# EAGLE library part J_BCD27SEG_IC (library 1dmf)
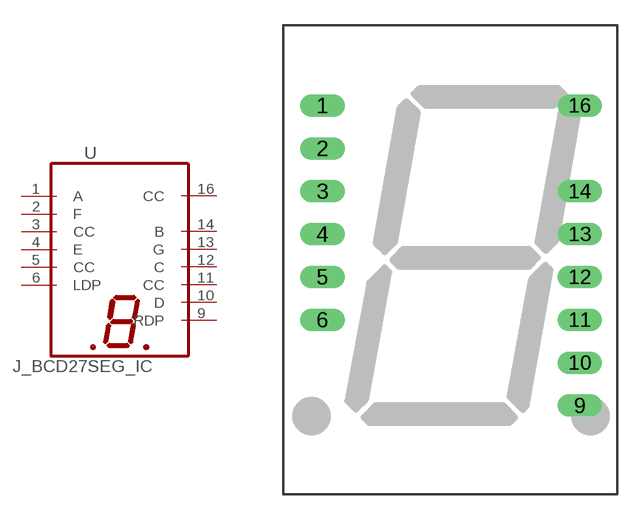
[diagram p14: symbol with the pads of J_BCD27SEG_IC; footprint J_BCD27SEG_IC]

Designator prefix -

## J_BCD27SEG_IC  [J_BCD27SEG_IC]
1  A  in
2  F  in
3  CC  out
4  E  in
5  CC  out
6  LDP  in
9  RDP  in
10  D  in
11  CC  out
12  C  in
13  G  in
14  B  in
16  CC  out

## Footprint J_BCD27SEG_IC (pad centres in mm)
drill 0.813 long: 1 -7.62,8.89; 2 -7.62,6.35; 3 -7.62,3.81; 4 -7.62,1.27; 5 -7.62,-1.27; 6 -7.62,-3.81; 9 7.62,-8.89; 10 7.62,-6.35; 11 7.62,-3.81; 12 7.62,-1.27; 13 7.62,1.27; 14 7.62,3.81; 16 7.62,8.89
